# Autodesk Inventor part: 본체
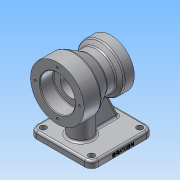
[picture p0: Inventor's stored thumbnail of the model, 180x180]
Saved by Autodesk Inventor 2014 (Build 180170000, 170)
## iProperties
Created: 2019-01
Part Number: 본체
Material: 알루미늄 6061
Document SubType Name: Modeling
Designer: NET
Density: 2.71 g/cm^3
Appearance: 알루미늄 - 평지
Mass: 902.15 g
Surface Area: 600.961 cm^2
Volume: 332.897 cm^3
Author: NET
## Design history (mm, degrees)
sketch "스케치1"
  geometry: L1 (0, 0)-(25, 0); L2 (25, 0)-(25, 40); L3 (25, 40)-(0, 40); L4 (0, 40)-(0, 0); L5 (25, 40)-(45.785, 28); L6 (45.785, 28)-(59.126, 28); L7 (59.126, 28)-(65, 35); L8 (65, 35)-(80, 35); L9 (80, 35)-(80, 0); L10 (80, 0)-(25, 0)
  constraints: 20 end point, 3 parallel, 3 perpendicular, 1 collinear, 1 horizontal
  dimensions: "d0" = 80 distance between parallel lines of L9 L4; "d1" = 25 distance of L2.end L3.end; "d2" = 15 distance of L7.end L8.end; "d3" = 80 diameter of L3 L1; "d4" = 56 diameter of L6 L10; "d5" = 30 deg angle of L6 L5; "d6" = 50 deg angle of L6 L7; "d7" = 70 diameter of L8 L10
revolve "회전1" sketch "스케치1" stored, may be unused: angle "d8" = 90 deg
node "작업 평면1"
sketch "스케치2"
  geometry: L1 (-5, -46)-(-97, -46); L2 (-97, -46)-(-97, 46); L3 (-97, 46)-(-5, 46); L4 (-5, 46)-(-5, -46); 1 further point
  constraints: 8 end point, 2 parallel, 1 horizontal, 1 perpendicular
  dimensions: "d10" = 92 distance of L1.end L2.end; "d11" = 92 distance of L1.start L1.end; "d12" = 46 distance from line of point (0, 0) L1; "d13" = 5 distance from line of point (0, 0) L4
extrude "돌출1" join sketch "스케치2" distance "d14" = 10; taper "d15" = 0 deg
fillet "모깎기1" dims "d16" = 10
sketch "스케치3"
  geometry: L1 (5, 36)-(5, -36) reference; C1 r 16 at (35, 0); 1 further point
  constraints: 1 centre point
  dimensions: "d17" = 32 diameter of C1; "d18" = 30 distance from line of L1 C1.centre; "d19" = 0 vertical distance of point (0, 0) C1.centre
extrude "돌출2" join sketch "스케치3" stored distance "d20" = 10; taper "d21" = 0 deg
sketch "스케치5"
  geometry: L1 (87, -70)-(97, -70) reference; L2 (15, -70)-(87, -70) reference; L3 (97, -80)-(97, -70) reference; L4 (51, -70)-(51, -28) reference; L5 (44.431, -70)-(87, -70); L6 (87, -70)-(44.431, 21.29); L7 (44.431, 21.29)-(44.431, -70); 1 further point
  constraints: 6 end point, 2 perpendicular
  dimensions: "d25" = 10 distance from line of L3 L5.end; "d26" = 0 distance between parallel lines of L2 L5; "d27" = 25 deg angle of L3 L6; "d32" = 6.56932 distance between parallel lines of L4 L7
extrude "돌출3" join sketch "스케치5" stored distance "d28" = 10; taper "d29" = 0 deg
fillet "모깎기2" dims "d30" = 3
fillet "모깎기4" dims "d33" = 3
fillet "모깎기5" dims "d34" = 3
sketch "스케치6"
  geometry: A1 r 7 centre (15, -36) between (8, -36) and (15, -43) reference; A2 r 7 centre (87, -36) between (87, -43) and (94, -36) reference; A3 r 7 centre (87, 36) between (94, 36) and (87, 43) reference; A4 r 7 centre (15, 36) between (15, 43) and (8, 36) reference; 5 further points
  constraints: 4 coincident
hole "구멍1" sketch "스케치6" at (15, 36), (87, 36), (87, -36), (15, -36) diameter "d35" = 9; stored, may be unused: countersink angle "d39" = 90 deg, drill point angle "d41" = 118 deg; dims "d36" = 6, "d37" = 4, "d38" = 2, "d40" = 8
sketch "스케치7"
  geometry: L1 (0, 26)-(20, 26); L2 (20, 26)-(20, 0); L3 (20, 0)-(0, 0); L4 (0, 0)-(0, 26); L5 (20, 16)-(63, 16); L6 (63, 16)-(63, 0); L7 (63, 0)-(20, 0); L8 (20, 0)-(20, 16); L9 (63, 0)-(80, 0); L10 (80, 0)-(80, 20); L11 (80, 20)-(63, 20); L12 (63, 20)-(63, 0); L13 (0, -40)-(0, 40) reference; L14 (80, -35)-(80, 35) reference; 1 further point
  constraints: 24 end point, 6 parallel, 3 horizontal, 3 perpendicular, 1 point on line
  dimensions: "d42" = 0 distance between parallel lines of L13 L4; "d44" = 0 distance between parallel lines of L14 L10; "d45" = 0 distance from line of point (0, 0) L3; "d46" = 26 distance between parallel lines of L3 L1; "d47" = 20 distance between parallel lines of L9 L11; "d48" = 16 distance between parallel lines of L7 L5; "d49" = 20 distance of L1.start L1.end; "d50" = 17 distance of L10.end L11.end
revolve "회전2" sketch "스케치7" stored, may be unused: angle "d51" = 90 deg
sketch "스케치8"
  geometry: C1 r 40 at (0, 0) reference; A1 r 33 centre (0, 0) between (0, 33) and (33, 0); 2 further points
  constraints: 4 point on circle, 1 centre point, 1 coincident
  dimensions: "d52" = 66 diameter of A1
hole "구멍2" sketch "스케치8" at (0, 33), (33, 0), (0, -33), (-33, 0) diameter "d53" = 3.242; stored, may be unused: countersink angle "d57" = 90 deg, drill point angle "d59" = 118 deg; dims "d54" = 9, "d55" = 4, "d56" = 2, "d58" = 11
sketch "스케치9"
  geometry: C1 r 35 at (0, 0) reference; A1 r 27.5 centre (0, 0) between (0, 27.5) and (27.5, 0); 2 further points
  constraints: 4 point on circle, 1 centre point, 1 coincident
  dimensions: "d60" = 55 diameter of A1
hole "구멍3" sketch "스케치9" at (0, 27.5), (27.5, 0), (0, -27.5), (-27.5, 0) diameter "d61" = 3.242; stored, may be unused: countersink angle "d65" = 90 deg, drill point angle "d67" = 118 deg; dims "d62" = 9, "d63" = 4, "d64" = 2, "d66" = 11
chamfer "모따기1" distance "d68" = 1; stored, may be unused: second distance "d69" = 2, angle "d70" = 45 deg
fillet "모깎기6" dims "d71" = 1
fillet "모깎기7" dims "d72" = 0.6
sketch "스케치10"
  geometry: L1 (-10, 7)-(-10, 0) reference; L2 (82, 0)-(72, 0) reference; 2 further points
  constraints: 1 other
  dimensions: "d73" = 46 distance from line of L1 point (36, 4); "d74" = 4 distance from line of L2 point (36, 4)
feature "엠보싱1" sketch "스케치10" dims "d16" = 10, "d75" = 0.5, "d76" = 0
fillet "모깎기8" dims "d77" = 3
node "솔리드1"
